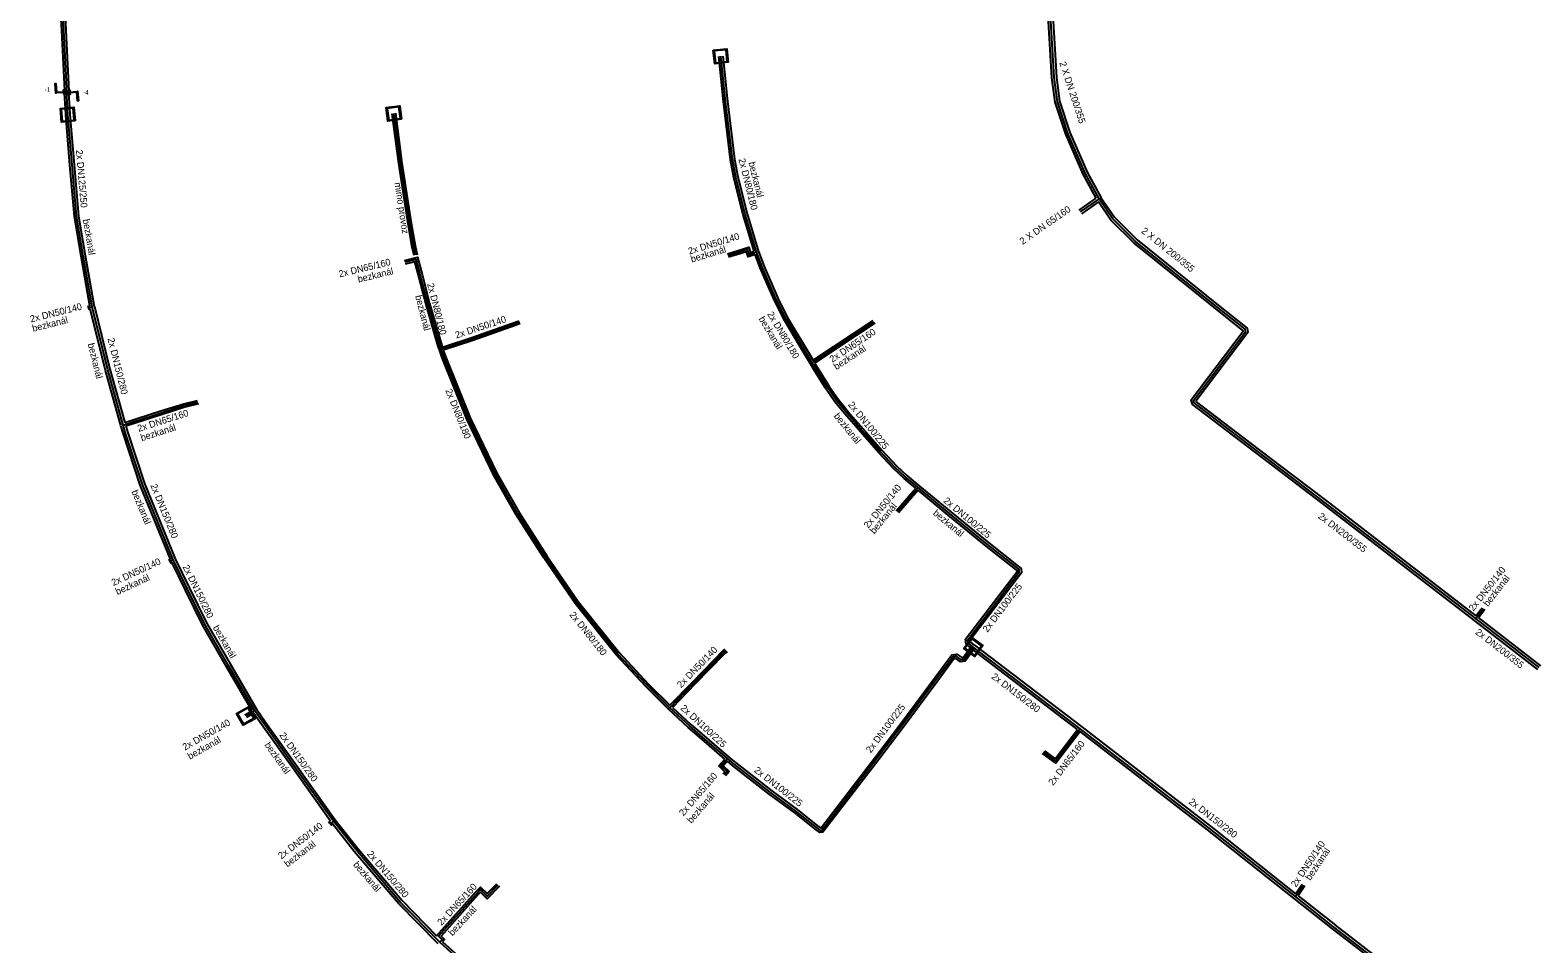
# Model space of a CAD drawing. Extents: x -606118 to -604472, y -1157869 to -1156854.
# Drawn here: x -606115.5 to -605782.8, y -1157542.5 to -1157340.8 of the extents above; entities that cross this region are included whole.
import ezdxf

# ---------------------------------------------------------------- set-up
doc = ezdxf.new("R2010")
doc.units = 0
for name, color, linetype in [('Osa trasy teplovodu', 7, 'Continuous'), ('Teplovod - trasa - okraj', 7, 'Continuous'), ('Teplovod - trasa popis', 7, 'Continuous'), ('Teplovod - trasa popis 2', 7, 'Continuous'), ('Teplovod - trasa popis 3', 7, 'Continuous'), ('výška krytí', 7, 'Continuous'), ('Výšková kóta trasy teplovodu', 7, 'Continuous'), ('Šachta trasy teplovodu', 7, 'Continuous')]:
    doc.layers.add(name, color=color, linetype=linetype)

msp = doc.modelspace()

# ---------------------------------------------------------------- linework, layer by layer
at = {"layer": 'Osa trasy teplovodu'}
for p, q in [((-605879.63, -1157378), (-605883.77, -1157380.9)), ((-606101.84, -1157401.87), (-606102.81, -1157402.12)), ((-606081.5, -1157423.64), (-606078.49, -1157422.91)), ((-605919.54, -1157441.75), (-605920.31, -1157442.69)), ((-605920.31, -1157442.69), (-605924.13, -1157447.13)), ((-606083.95, -1157457.69), (-606084.85, -1157458.11)), ((-605796.5, -1157470.68), (-605794.78, -1157468.48)), ((-605883.78, -1157495), (-605907.39, -1157476.96)), ((-606065.94, -1157491.07), (-606067.94, -1157492.19)), ((-605961.63, -1157501.59), (-605962.53, -1157502.61)), ((-606048.6, -1157515.4), (-606049.45, -1157516.04)), ((-605836.26, -1157532.06), (-605834.52, -1157529.47)), ((-605827.81, -1157538.77), (-605836.26, -1157532.06))]:
    msp.add_line(p, q, dxfattribs=at)
for points in [[(-606107.22, -1157359.44), (-606107.26, -1157357.98), (-606107.44, -1157355.35), (-606107.48, -1157354.68), (-606107.4, -1157354.2), (-606107.44, -1157353.61), (-606108.12, -1157340.88), (-606108.41, -1157333.99)], [(-605879.63, -1157378), (-605882.69, -1157372.34), (-605886.51, -1157363.58), (-605888.82, -1157356.57), (-605889.54, -1157351.26), (-605890.51, -1157335.08)], [(-605955.21, -1157389.82), (-605957.75, -1157381.44), (-605959.8, -1157373.26), (-605960.56, -1157369.36), (-605962.12, -1157355.92), (-605962.59, -1157351.47), (-605963.12, -1157346.54)], [(-606030.43, -1157390.46), (-606030.92, -1157388.35), (-606031.78, -1157383.47), (-606033.82, -1157370.17), (-606035.26, -1157359.17)], [(-606101.84, -1157401.87), (-606103.8, -1157390.6), (-606105.31, -1157381.87), (-606106.28, -1157370.51), (-606107.22, -1157359.44)], [(-605854.02, -1157401.56), (-605871.56, -1157387.42), (-605876.64, -1157382.37), (-605879.63, -1157378)], [(-606029.35, -1157395.08), (-606030.32, -1157391.4), (-606032.84, -1157392.02)], [(-605955.21, -1157389.82), (-605956.83, -1157390.33), (-605957.21, -1157389.2), (-605961.53, -1157390.52)], [(-605948.61, -1157404.75), (-605950.94, -1157400.11), (-605953.99, -1157393.11), (-605955.21, -1157389.82)], [(-606024.83, -1157411.24), (-606025.07, -1157410.52), (-606027.76, -1157401.25), (-606029.35, -1157395.08)], [(-606095.03, -1157427.95), (-606098.4, -1157415.77), (-606101.84, -1157401.87)], [(-605796.5, -1157470.68), (-605830.05, -1157444.88), (-605840.24, -1157437.1), (-605858.66, -1157423.08), (-605858.78, -1157422.52), (-605853.05, -1157414.95), (-605847.33, -1157407.38), (-605847.4, -1157406.81), (-605854.02, -1157401.56)], [(-606024.83, -1157411.24), (-606017.96, -1157408.96), (-606008.02, -1157405.45), (-606007.86, -1157405.9)], [(-605942.96, -1157414.21), (-605945.27, -1157410.33), (-605948.61, -1157404.75)], [(-605942.96, -1157414.21), (-605933.44, -1157407.9), (-605929.32, -1157405.16)], [(-606007.97, -1157447.45), (-606012.91, -1157438.74), (-606018.8, -1157426.51), (-606024.24, -1157412.94), (-606024.83, -1157411.24)], [(-605919.54, -1157441.75), (-605920.94, -1157440.59), (-605922.34, -1157439.43), (-605924.68, -1157437.23), (-605927.92, -1157433.79), (-605931.44, -1157429.76), (-605934.96, -1157425.73), (-605936.27, -1157424.13), (-605937.57, -1157422.52), (-605939.63, -1157419.55), (-605942, -1157415.81), (-605942.96, -1157414.21)], [(-606095.03, -1157427.95), (-606086.53, -1157425.22), (-606081.5, -1157423.64)], [(-606083.95, -1157457.69), (-606090.75, -1157441.06), (-606094.48, -1157429.82), (-606095.03, -1157427.95)], [(-605897.73, -1157459.48), (-605904.64, -1157454.02), (-605912.66, -1157447.46), (-605919.54, -1157441.75)], [(-605974.36, -1157490.36), (-605979.35, -1157485.41), (-605985.87, -1157478.43), (-605994.92, -1157467.12), (-606001.85, -1157457.02), (-606007.97, -1157447.45)], [(-606065.94, -1157491.07), (-606071.8, -1157480.94), (-606077.07, -1157471.85), (-606080.86, -1157464.04), (-606083.95, -1157457.69)], [(-605907.39, -1157476.96), (-605908.53, -1157476.05), (-605908.62, -1157475.38), (-605897.23, -1157460.44), (-605897.24, -1157459.86), (-605897.73, -1157459.48)], [(-605782.5, -1157481.51), (-605796.41, -1157470.75), (-605796.5, -1157470.68)], [(-605974.36, -1157490.36), (-605969.1, -1157484.93), (-605962.37, -1157478.01), (-605961.99, -1157478.4)], [(-605907.39, -1157476.96), (-605909.4, -1157479.68), (-605910.06, -1157479.76), (-605911.14, -1157478.98), (-605911.85, -1157479.1), (-605915.59, -1157484.12), (-605923.47, -1157494.72), (-605928.59, -1157501.49), (-605940.81, -1157517.42), (-605941.13, -1157517.46), (-605941.76, -1157516.97)], [(-606048.6, -1157515.4), (-606057.3, -1157503.2), (-606063.98, -1157493.83), (-606065.94, -1157491.07)], [(-605961.63, -1157501.59), (-605967.61, -1157496.45), (-605970.01, -1157494.36), (-605974.36, -1157490.36)], [(-605883.78, -1157495), (-605889.22, -1157502.13), (-605891.88, -1157500.17)], [(-605836.26, -1157532.06), (-605855.37, -1157516.92), (-605883.78, -1157495)], [(-605941.76, -1157516.97), (-605946.53, -1157513.18), (-605952.13, -1157509.08), (-605960.14, -1157502.82), (-605961.63, -1157501.59)], [(-605962.53, -1157502.61), (-605963.05, -1157503.18), (-605961.71, -1157504.45), (-605962.33, -1157505.18)], [(-606025.13, -1157542.12), (-606033.83, -1157533.26), (-606043.61, -1157521.75), (-606048.6, -1157515.4)], [(-606025.13, -1157542.12), (-606024.61, -1157541.56), (-606025.4, -1157540.78), (-606017.03, -1157531.41)], [(-606017.03, -1157531.41), (-606016.13, -1157530.5), (-606014.68, -1157531.97), (-606012.22, -1157529.48)], [(-605803.26, -1157557.65), (-605803.42, -1157557.53), (-605827.81, -1157538.77)], [(-606007.6, -1157557.8), (-606011.29, -1157554.53), (-606014.85, -1157551.39), (-606019.95, -1157546.8), (-606025.13, -1157542.12)]]:
    msp.add_lwpolyline(points, dxfattribs=at)
at = {"layer": 'Teplovod - trasa - okraj'}
for p, q in [((-605884.05, -1157380.49), (-605880.28, -1157377.85)), ((-605879.76, -1157378.7), (-605883.48, -1157381.31)), ((-606102.89, -1157401.78), (-606102.34, -1157401.64)), ((-606102.24, -1157402.33), (-606102.72, -1157402.45)), ((-606081.59, -1157423.25), (-606078.58, -1157422.52)), ((-606078.39, -1157423.3), (-606081.4, -1157424.03)), ((-605920.58, -1157442.47), (-605920.1, -1157441.88)), ((-605919.56, -1157442.32), (-605920.04, -1157442.91)), ((-605924.39, -1157446.9), (-605920.58, -1157442.46)), ((-605920.05, -1157442.92), (-605923.86, -1157447.36)), ((-606085, -1157457.79), (-606084.54, -1157457.58)), ((-606084.26, -1157458.22), (-606084.71, -1157458.43)), ((-605796.47, -1157470.07), (-605795.06, -1157468.27)), ((-605794.51, -1157468.7), (-605795.91, -1157470.5)), ((-605795.91, -1157470.5), (-605782.19, -1157481.11)), ((-605884.36, -1157495.18), (-605907.33, -1157477.64)), ((-605907.09, -1157476.56), (-605883.47, -1157494.6)), ((-606068.11, -1157491.89), (-606066.55, -1157491.01)), ((-606066.17, -1157491.6), (-606067.76, -1157492.5)), ((-605962.8, -1157502.38), (-605962.19, -1157501.69)), ((-605961.66, -1157502.15), (-605962.27, -1157502.84)), ((-606049.66, -1157515.76), (-606049.21, -1157515.42)), ((-606048.79, -1157515.98), (-606049.23, -1157516.32)), ((-606025.85, -1157540.68), (-606017.32, -1157531.14)), ((-605836.26, -1157531.43), (-605834.81, -1157529.28)), ((-605834.23, -1157529.67), (-605835.71, -1157531.87)), ((-605835.71, -1157531.87), (-605827.49, -1157538.37)), ((-605828.12, -1157539.16), (-605836.57, -1157532.46)), ((-605827.5, -1157538.37), (-605803.51, -1157556.83))]:
    msp.add_line(p, q, dxfattribs=at)
for points in [[(-606107.67, -1157359.46), (-606107.71, -1157358), (-606107.94, -1157354.66), (-606107.86, -1157354.18), (-606108.56, -1157340.9), (-606108.86, -1157334.01)], [(-606107.96, -1157333.97), (-606107.67, -1157340.85), (-606106.95, -1157354.22), (-606107.03, -1157354.7), (-606106.81, -1157357.96), (-606106.77, -1157359.41)], [(-605880.28, -1157377.85), (-605883.14, -1157372.56), (-605886.98, -1157363.75), (-605889.31, -1157356.68), (-605890.03, -1157351.31), (-605891.01, -1157335.1)], [(-605890.01, -1157335.05), (-605889.04, -1157351.22), (-605888.33, -1157356.45), (-605886.05, -1157363.4), (-605882.24, -1157372.13), (-605879.19, -1157377.77)], [(-605955.76, -1157389.57), (-605958.19, -1157381.56), (-605960.24, -1157373.36), (-605961, -1157369.43), (-605962.57, -1157355.97), (-605963.04, -1157351.51), (-605963.56, -1157346.58)], [(-605962.67, -1157346.49), (-605962.14, -1157351.42), (-605961.67, -1157355.88), (-605960.11, -1157369.29), (-605959.36, -1157373.17), (-605957.32, -1157381.32), (-605954.78, -1157389.69)], [(-606034.91, -1157359.13), (-606033.47, -1157370.12), (-606031.43, -1157383.41), (-606030.58, -1157388.28), (-606030.09, -1157390.38)], [(-606102.34, -1157401.64), (-606104.24, -1157390.67), (-606105.76, -1157381.93), (-606106.73, -1157370.55), (-606107.67, -1157359.46)], [(-606106.77, -1157359.41), (-606105.83, -1157370.48), (-606104.87, -1157381.82), (-606103.36, -1157390.52), (-606101.4, -1157401.79)], [(-606030.77, -1157390.54), (-606031.27, -1157388.42), (-606032.12, -1157383.52), (-606034.17, -1157370.21), (-606035.61, -1157359.22)], [(-605854.33, -1157401.95), (-605871.89, -1157387.79), (-605877.03, -1157382.7), (-605879.76, -1157378.7)], [(-605879.22, -1157377.72), (-605876.26, -1157382.05), (-605871.22, -1157387.04), (-605853.7, -1157401.17)], [(-605961.64, -1157390.14), (-605956.95, -1157388.7), (-605956.58, -1157389.83), (-605955.76, -1157389.57)], [(-606032.94, -1157391.63), (-606030.03, -1157390.92), (-606028.96, -1157394.98)], [(-606029.73, -1157395.19), (-606030.6, -1157391.89), (-606032.75, -1157392.41)], [(-605955.5, -1157390.33), (-605957.09, -1157390.83), (-605957.46, -1157389.69), (-605961.41, -1157390.9)], [(-605949.01, -1157404.95), (-605951.35, -1157400.3), (-605954.41, -1157393.28), (-605955.5, -1157390.33)], [(-605954.79, -1157389.66), (-605953.57, -1157392.94), (-605950.54, -1157399.92), (-605948.21, -1157404.55)], [(-606025.22, -1157411.37), (-606025.45, -1157410.64), (-606028.15, -1157401.36), (-606029.73, -1157395.18)], [(-606028.96, -1157394.98), (-606027.37, -1157401.14), (-606024.69, -1157410.4), (-606024.45, -1157411.12)], [(-606095.51, -1157428.08), (-606098.89, -1157415.9), (-606102.24, -1157402.33)], [(-606101.35, -1157401.75), (-606097.92, -1157415.64), (-606094.66, -1157427.41)], [(-605796.8, -1157471.07), (-605830.35, -1157445.27), (-605840.55, -1157437.5), (-605859.11, -1157423.36), (-605859.31, -1157422.4), (-605847.85, -1157407.24), (-605847.87, -1157407.08), (-605854.33, -1157401.95)], [(-605853.71, -1157401.17), (-605846.93, -1157406.55), (-605846.81, -1157407.52), (-605858.24, -1157422.64), (-605858.21, -1157422.8), (-605839.94, -1157436.7), (-605829.74, -1157444.48), (-605796.47, -1157470.07)], [(-606024.56, -1157410.78), (-606018.07, -1157408.63), (-606007.81, -1157405), (-606007.53, -1157405.78)], [(-605943.35, -1157414.44), (-605945.66, -1157410.57), (-605949, -1157404.98)], [(-605948.22, -1157404.52), (-605944.89, -1157410.1), (-605942.76, -1157413.66)], [(-605942.76, -1157413.66), (-605933.63, -1157407.61), (-605929.52, -1157404.87)], [(-605929.13, -1157405.45), (-605933.24, -1157408.19), (-605942.41, -1157414.26)], [(-606008.18, -1157406.02), (-606008.23, -1157405.89), (-606017.85, -1157409.29), (-606024.34, -1157411.45)], [(-606008.31, -1157447.66), (-606013.26, -1157438.92), (-606019.16, -1157426.67), (-606024.62, -1157413.08), (-606025.21, -1157411.37)], [(-606024.34, -1157411.45), (-606023.87, -1157412.8), (-606018.43, -1157426.34), (-606012.56, -1157438.55), (-606007.62, -1157447.25)], [(-605920.1, -1157441.88), (-605921.23, -1157440.94), (-605922.64, -1157439.77), (-605925, -1157437.55), (-605928.26, -1157434.09), (-605931.78, -1157430.06), (-605935.31, -1157426.02), (-605936.62, -1157424.41), (-605937.93, -1157422.79), (-605940, -1157419.8), (-605942.39, -1157416.04), (-605943.35, -1157414.44)], [(-605942.41, -1157414.26), (-605941.62, -1157415.57), (-605939.25, -1157419.3), (-605937.21, -1157422.25), (-605935.92, -1157423.84), (-605934.62, -1157425.44), (-605931.1, -1157429.46), (-605927.59, -1157433.49), (-605924.36, -1157436.92), (-605922.04, -1157439.1), (-605920.66, -1157440.25), (-605919.26, -1157441.41)], [(-606094.66, -1157427.41), (-606086.65, -1157424.84), (-606081.62, -1157423.26)], [(-606081.38, -1157424.02), (-606086.41, -1157425.6), (-606094.44, -1157428.18)], [(-606084.54, -1157457.58), (-606091.22, -1157441.23), (-606094.95, -1157429.97), (-606095.51, -1157428.09)], [(-606094.44, -1157428.18), (-606094, -1157429.67), (-606090.28, -1157440.88), (-606083.49, -1157457.5)], [(-605898.01, -1157459.83), (-605904.92, -1157454.37), (-605912.94, -1157447.81), (-605919.56, -1157442.32)], [(-605919.26, -1157441.41), (-605912.37, -1157447.12), (-605904.36, -1157453.67), (-605897.45, -1157459.13)], [(-605974.64, -1157490.64), (-605979.64, -1157485.69), (-605986.18, -1157478.69), (-605995.24, -1157467.36), (-606002.18, -1157457.24), (-606008.31, -1157447.66)], [(-606007.62, -1157447.25), (-606001.52, -1157456.8), (-605994.6, -1157466.88), (-605985.57, -1157478.17), (-605979.06, -1157485.13), (-605974.33, -1157489.82)], [(-606066.55, -1157491.01), (-606072.24, -1157481.19), (-606077.51, -1157472.08), (-606081.31, -1157464.26), (-606084.26, -1157458.22)], [(-606083.51, -1157457.47), (-606080.41, -1157463.82), (-606076.62, -1157471.61), (-606071.37, -1157480.69), (-606065.51, -1157490.82)], [(-605908.01, -1157477.04), (-605908.96, -1157476.29), (-605909.09, -1157475.25), (-605897.68, -1157460.29), (-605897.69, -1157460.08), (-605898.01, -1157459.83)], [(-605897.45, -1157459.13), (-605896.79, -1157459.64), (-605896.78, -1157460.59), (-605908.15, -1157475.5), (-605908.11, -1157475.81), (-605907.11, -1157476.61)], [(-605782.8, -1157481.9), (-605796.71, -1157471.15), (-605796.8, -1157471.07)], [(-605974.33, -1157489.82), (-605969.35, -1157484.69), (-605962.37, -1157477.5), (-605961.74, -1157478.16)], [(-605962.25, -1157478.65), (-605962.38, -1157478.51), (-605968.84, -1157485.17), (-605973.79, -1157490.27)], [(-605907.03, -1157477.23), (-605909.16, -1157480.11), (-605910.18, -1157480.22), (-605911.25, -1157479.45), (-605911.6, -1157479.51), (-605915.23, -1157484.39), (-605923.11, -1157494.99), (-605928.23, -1157501.76), (-605940.57, -1157517.84), (-605941.26, -1157517.93), (-605942.03, -1157517.32)], [(-605941.48, -1157516.61), (-605941.03, -1157516.96), (-605928.95, -1157501.21), (-605923.83, -1157494.45), (-605915.95, -1157483.86), (-605912.11, -1157478.69), (-605911.02, -1157478.5), (-605909.94, -1157479.29), (-605909.65, -1157479.26), (-605907.75, -1157476.69)], [(-606049.21, -1157515.42), (-606057.71, -1157503.49), (-606064.38, -1157494.12), (-606066.17, -1157491.6)], [(-606065.53, -1157490.78), (-606063.57, -1157493.54), (-606056.89, -1157502.91), (-606048.2, -1157515.11)], [(-605962.19, -1157501.69), (-605967.9, -1157496.79), (-605970.31, -1157494.7), (-605974.66, -1157490.69)], [(-605973.79, -1157490.27), (-605969.71, -1157494.03), (-605967.31, -1157496.11), (-605961.34, -1157501.24)], [(-605891.67, -1157499.88), (-605889.29, -1157501.64), (-605884.36, -1157495.18)], [(-605883.47, -1157494.6), (-605855.07, -1157516.53), (-605836.26, -1157531.43)], [(-605883.8, -1157495.61), (-605889.15, -1157502.61), (-605892.08, -1157500.45)], [(-605836.57, -1157532.46), (-605855.68, -1157517.31), (-605883.8, -1157495.61)], [(-605942.04, -1157517.32), (-605946.8, -1157513.53), (-605952.4, -1157509.44), (-605960.42, -1157503.17), (-605961.66, -1157502.15)], [(-605961.34, -1157501.24), (-605959.85, -1157502.47), (-605951.86, -1157508.72), (-605946.26, -1157512.82), (-605941.48, -1157516.62)], [(-605962.6, -1157504.95), (-605962.19, -1157504.48), (-605963.54, -1157503.2), (-605962.79, -1157502.38)], [(-605962.28, -1157502.85), (-605962.56, -1157503.16), (-605961.23, -1157504.42), (-605962.06, -1157505.4)], [(-606048.21, -1157515.09), (-606043.23, -1157521.44), (-606033.46, -1157532.92), (-606025.85, -1157540.68)], [(-606025.49, -1157542.47), (-606034.2, -1157533.59), (-606044, -1157522.07), (-606048.79, -1157515.98)], [(-606016.74, -1157531.69), (-606024.85, -1157540.76), (-606024.06, -1157541.55), (-606024.49, -1157542.02)], [(-606017.31, -1157531.13), (-606016.13, -1157529.93), (-606014.68, -1157531.4), (-606012.51, -1157529.2)], [(-606011.94, -1157529.77), (-606014.68, -1157532.54), (-606016.13, -1157531.07), (-606016.74, -1157531.69)], [(-606024.49, -1157542.02), (-606019.61, -1157546.43), (-606014.52, -1157551.02), (-606010.96, -1157554.16), (-606007.27, -1157557.42)], [(-605803.56, -1157558.05), (-605803.72, -1157557.93), (-605828.11, -1157539.16)]]:
    msp.add_lwpolyline(points, dxfattribs=at)
at = {"layer": 'Výšková kóta trasy teplovodu'}
for points in [[(-606108.15, -1157354.36), (-606108.18, -1157353.97), (-606107.37, -1157354.38), (-606108.11, -1157354.9), (-606108.14, -1157354.52), (-606109.73, -1157354.64), (-606109.73, -1157354.64), (-606109.83, -1157354.65), (-606109.99, -1157352.58), (-606109.82, -1157352.56), (-606109.67, -1157354.48), (-606108.15, -1157354.36)], [(-606106.73, -1157354.59), (-606106.7, -1157354.98), (-606107.51, -1157354.59), (-606106.79, -1157354.05), (-606106.75, -1157354.44), (-606105.16, -1157354.29), (-606105.16, -1157354.29), (-606105.06, -1157354.28), (-606104.87, -1157356.35), (-606105.04, -1157356.37), (-606105.22, -1157354.45), (-606106.73, -1157354.59)]]:
    msp.add_lwpolyline(points, dxfattribs=at)
at = {"layer": 'Šachta trasy teplovodu'}
for points in [[(-605964.77, -1157345.2), (-605961.78, -1157344.88), (-605961.46, -1157347.87), (-605964.45, -1157348.19), (-605964.77, -1157345.2)], [(-605964.28, -1157347.98), (-605961.67, -1157347.7), (-605961.94, -1157345.09), (-605964.56, -1157345.37), (-605964.28, -1157347.98)], [(-606105.6, -1157360.81), (-606108.59, -1157361.06), (-606108.85, -1157358.07), (-606105.85, -1157357.81), (-606105.6, -1157360.81)], [(-606106.02, -1157358.02), (-606108.64, -1157358.24), (-606108.42, -1157360.86), (-606105.8, -1157360.64), (-606106.02, -1157358.02)], [(-606033.58, -1157360.46), (-606036.56, -1157360.86), (-606036.95, -1157357.88), (-606033.97, -1157357.48), (-606033.58, -1157360.46)], [(-606034.13, -1157357.7), (-606036.74, -1157358.04), (-606036.4, -1157360.65), (-606033.79, -1157360.3), (-606034.13, -1157357.7)], [(-605907.7, -1157474.86), (-605905.29, -1157476.65), (-605907.07, -1157479.06), (-605909.49, -1157477.28), (-605907.7, -1157474.86)], [(-605909.23, -1157477.24), (-605907.11, -1157478.8), (-605905.55, -1157476.69), (-605907.66, -1157475.12), (-605909.23, -1157477.24)], [(-606067.36, -1157490.15), (-606065.89, -1157492.77), (-606068.5, -1157494.24), (-606069.98, -1157491.62), (-606067.36, -1157490.15)], [(-606069.73, -1157491.7), (-606068.43, -1157493.99), (-606066.14, -1157492.69), (-606067.43, -1157490.4), (-606069.73, -1157491.7)]]:
    msp.add_lwpolyline(points, dxfattribs=at)

# ---------------------------------------------------------------- texts
at = {"layer": 'Teplovod - trasa popis'}
for s, rotation, p in [('2 X DN 200/355', 288.2017, (-605888.42, -1157347.99)), ('2x DN125/250', 274.8366, (-606105.42, -1157367.25)), ('2x DN80/180', 284.0963, (-605959.22, -1157369.26)), ('2 X DN 65/160', 34.9651, (-605896.51, -1157388.2)), ('2x DN50/140', 17.0491, (-605970.04, -1157390.33)), ('2 X DN 200/355', 321.1245, (-605870.44, -1157385.35)), ('2x DN65/160', 13.6685, (-606047.23, -1157395.37)), ('2x DN80/180', 284.1694, (-606027.92, -1157396.83)), ('2x DN50/140', 14.2229, (-606115.32, -1157405.31)), ('2x DN50/140', 18.3857, (-606021.44, -1157408.87)), ('2x DN80/180', 300.8561, (-605952.94, -1157403.44)), ('2x DN150/280', 283.8913, (-606098.45, -1157408.89)), ('2x DN65/160', 33.5039, (-605938.51, -1157414.22)), ('2x DN80/180', 291.8887, (-606023.93, -1157420.29)), ('2x DN65/160', 17.7725, (-606091.57, -1157429.48)), ('2x DN100/225', 309.0623, (-605935.13, -1157423.5)), ('2x DN150/280', 292.2266, (-606089.02, -1157441.27)), ('2x DN50/140', 50.6228, (-605930.57, -1157450.87)), ('2x DN100/225', 320.3281, (-605914.12, -1157444.88)), ('2x DN200/355', 322.4335, (-605831.42, -1157448.37)), ('2x DN50/140', 24.7619, (-606097.16, -1157463.5)), ('2x DN150/280', 295.9758, (-606081.92, -1157459.23)), ('2x DN50/140', 51.959, (-605797.02, -1157469.16)), ('2x DN100/225', 52.6619, (-605904.27, -1157473.82)), ('2x DN80/180', 308.6591, (-605996.6, -1157469.88)), ('2x DN200/355', 322.2788, (-605796.74, -1157473.94)), ('2x DN50/140', 45.8684, (-605971.86, -1157486.11)), ('2x DN150/280', 322.6207, (-605903.53, -1157483.75)), ('2x DN100/225', 317.3243, (-605972.13, -1157490.6)), ('2x DN100/225', 52.9083, (-605930.02, -1157500.46)), ('2x DN50/140', 29.4527, (-606081.38, -1157499.83)), ('2x DN150/280', 305.4861, (-606060.6, -1157496.42)), ('2x DN65/160', 52.6469, (-605889.78, -1157507.64)), ('2x DN65/160', 49.5095, (-605971.34, -1157514.38)), ('2x DN100/225', 322.0028, (-605955.9, -1157504.41)), ('2x DN150/280', 322.3396, (-605860, -1157511.38)), ('2x DN50/140', 37.4185, (-606060.08, -1157523.85)), ('2x DN150/280', 310.3731, (-606041.28, -1157522.69)), ('2x DN50/140', 56.1095, (-605836.18, -1157530.1)), ('2x DN65/160', 47.1972, (-606024.75, -1157538.56))]:
    msp.add_text(s, height=1.5, rotation=rotation, dxfattribs=at).set_placement(p)
at = {"layer": 'Teplovod - trasa popis 2'}
for rotation, p in [(284.0963, (-605957.01, -1157370.03)), (279.8504, (-606103.93, -1157382.6)), (17.0491, (-605969.51, -1157392.1)), (13.6685, (-606043.05, -1157396.52)), (284.4281, (-606030.57, -1157399.47)), (14.2229, (-606114.85, -1157407.37)), (300.8561, (-605954.81, -1157404.5)), (283.8913, (-606102.82, -1157410.05)), (33.5039, (-605937.6, -1157415.85)), (309.0623, (-605938.26, -1157426.02)), (17.7725, (-606090.88, -1157431.52)), (292.2266, (-606093.18, -1157442.62)), (50.6228, (-605929.22, -1157452.11)), (320.3281, (-605916.42, -1157447.63)), (24.7619, (-606096.27, -1157465.5)), (51.959, (-605793.82, -1157468.13)), (300.0488, (-606075.26, -1157472.66)), (29.4527, (-606080.27, -1157501.84)), (305.4861, (-606063.86, -1157498.61)), (49.5095, (-605969.58, -1157516)), (37.4185, (-606058.73, -1157525.65)), (56.1095, (-605833.01, -1157528.6)), (310.3731, (-606044.33, -1157525.05)), (47.1972, (-606022.3, -1157540.84))]:
    msp.add_text('bezkanál', height=1.5, rotation=rotation, dxfattribs=at).set_placement(p)
at = {"layer": 'Teplovod - trasa popis 3'}
msp.add_text('mimo provoz', height=1.5, rotation=278.7413, dxfattribs=at).set_placement((-606035.13, -1157374.49))
at = {"layer": 'výška krytí'}
for s, p in [('-1', (-606112.32, -1157354.38)), ('-4', (-606103.84, -1157354.99))]:
    msp.add_text(s, height=1, dxfattribs=at).set_placement(p)

doc.saveas('drawing.dxf')
